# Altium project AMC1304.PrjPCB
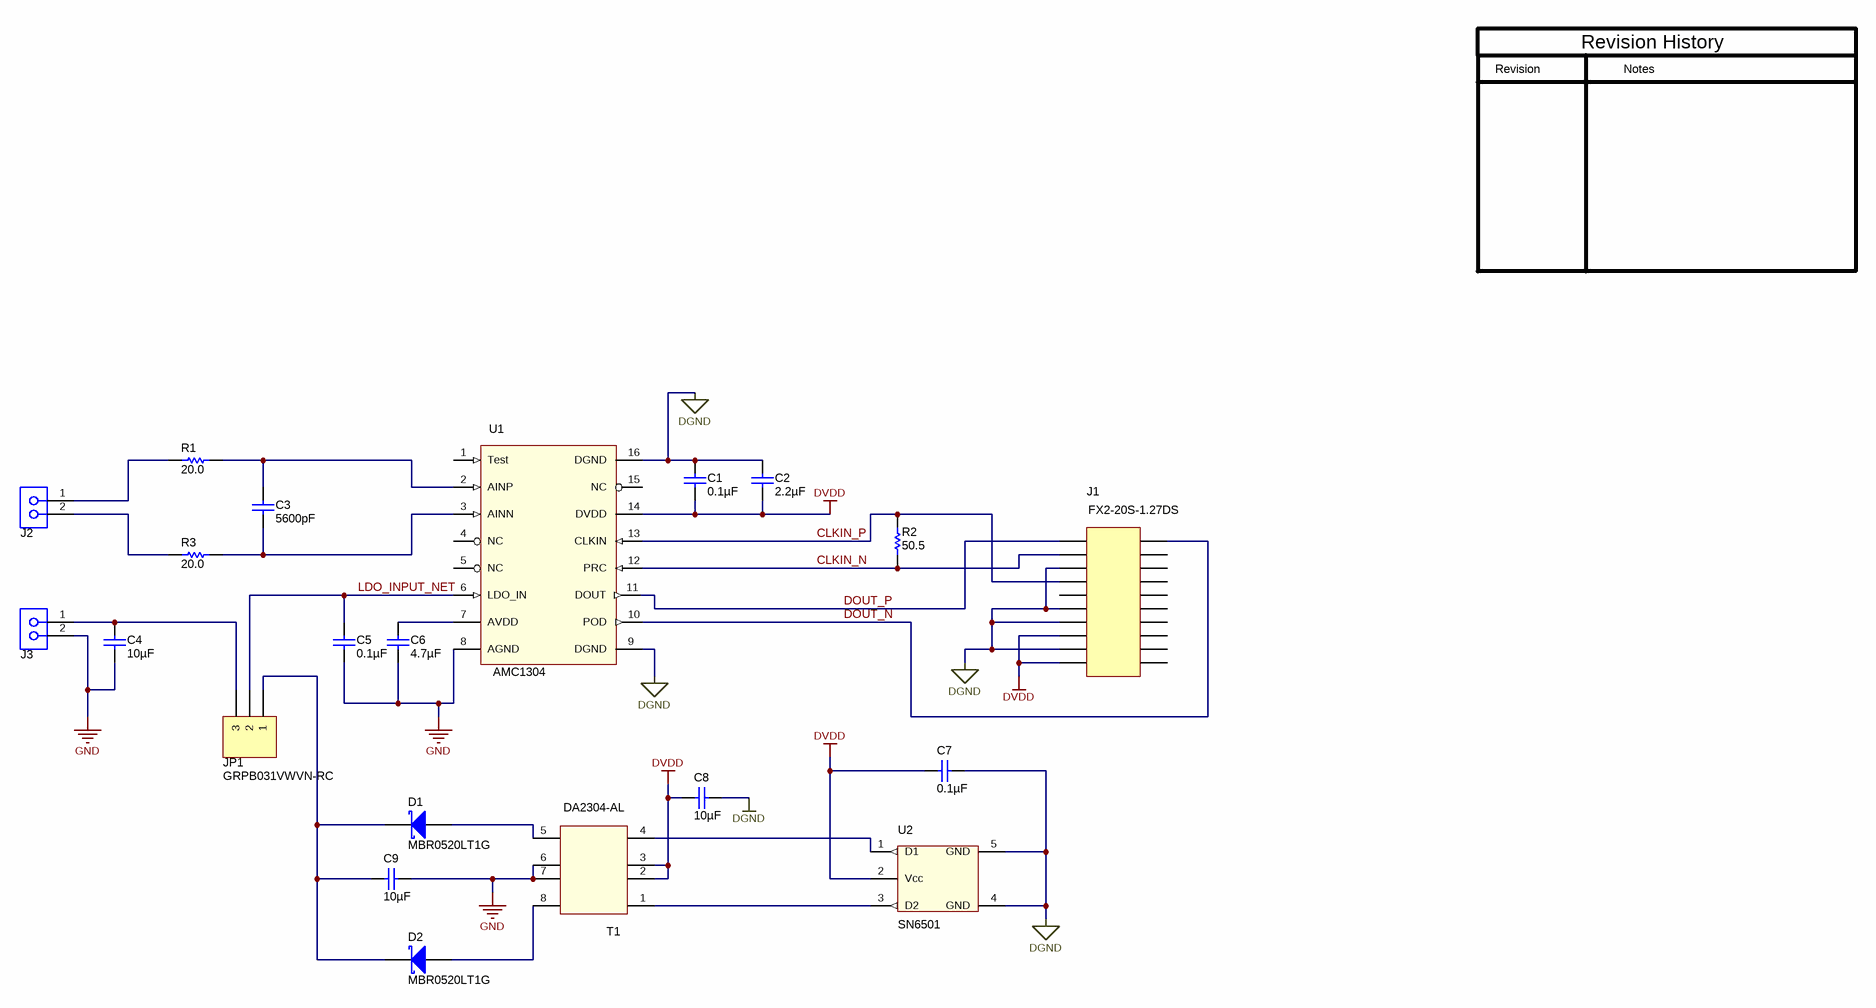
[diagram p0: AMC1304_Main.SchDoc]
CopyrightYear: 2014; PCB_Layout: Jose Duenas; PCB_Rev: E1; PRJ_Customer: Public Release; PRJ_Engineer: Jose Duenas; PRJ_Number: AMC1304EVM - TIPD; PRJ_Title: AMC1304 Evaluation Module - TIPD; SCH_Rev: E1; TechSupport: http://www.ti.com/support
1 sheet, 21 parts. Net scope: global (net labels, ports and power ports of the same name join across sheets).
Board file: AMC1304EVM.PcbDoc

## Sheet AMC1304_Main.SchDoc: Main Schematic
size 431 x 279 mm; Date: Not shown in title block; ApprovedBy: Not shown in title block; CheckedBy: Not shown in title block; Author: Not shown in title block; CompanyName: Not shown in title block; DrawnBy: Jose Duenas; Engineer: Not shown in title block; Organization: Not shown in title block; Address1: Not shown in title block; Address2: Not shown in title block; Address3: Not shown in title block; Address4: Not shown in title block; DocumentNumber: 2; Revision: Use project parameter SCH_Rev; SheetNumber: 2; SheetTotal: 3; PageSetup: Record=PageOptions|CenterHorizontal=True|CenterVertical=True|PrintScale=0.64|XCorrection=1.00|YCorrection=1.00|PrintKind=0|BorderSize=5000000|LeftOffset=0|BottomOffset=0|Orientation=2|PaperLength=1000|PaperWidth=1000|Scale=100|PaperSource=15|PrintQuality=600|MediaType=1|DitherType=10|PaperKind=Letter|PrintScaleMode=1

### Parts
C1  ValueDisplayed: 0.1µF  [1206]  (hidden comment: C3216C0G1E104J)
C2  ValueDisplayed: 2.2µF  [0805_HV]  (hidden comment: EMK212B7225KG-T)
C3  ValueDisplayed: 5600pF  [0805_HV]  (hidden comment: C2012C0G1E562J)
C4  ValueDisplayed: 10µF  [0805_HV]  (hidden comment: EMK212BJ106KG-T)
C5  ValueDisplayed: 0.1µF  [1206]  (hidden comment: C3216C0G1E104J)
C6  ValueDisplayed: 4.7µF  [0805_HV]  (hidden comment: C0805C475K8PACTU)
C7  ValueDisplayed: 0.1µF  [1206]  (hidden comment: C3216C0G1E104J)
C8  ValueDisplayed: 10µF  [0805_HV]  (hidden comment: EMK212BJ106KG-T)
C9  ValueDisplayed: 10µF  [0805_HV]  (hidden comment: EMK212BJ106KG-T)
D1  MBR0520LT1G  [SOD-123]
D2  MBR0520LT1G  [SOD-123]
J1  FX2-20S-1.27DS  [FX2_20S_1p27_DS_recept_good]
J2  1751248  [CONN_1751248]  (value not drawn)
J3  1751248  [CONN_1751248]  (value not drawn)
JP1  GRPB031VWVN-RC  [MHDR1X3]
R1  value 20.0  [0603]  (hidden comment: RT0603BRD0720RL)
R2  value 50.5  [0603]  (hidden comment: RT0603BRD0750R5L)
R3  value 20.0  [0603]  (hidden comment: RT0603BRD0720RL)
T1  DA2304-AL  [DA230x_land_patt]
U1  AMC1304  [DW0016_HV_ISO_JAD]
U2  SN6501  [DBV0005A_N]

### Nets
DGND: C1.1 C2.1 C7.2 C8.1 J1.a3 J1.a6 J1.a7 J1.a9 U1.9(DGND) U1.16(DGND) U2.4(GND) U2.5(GND)
DVDD: C1.2 C2.2 C7.1 C8.2 J1.a8 J1.a10 T1.2 T1.3 U1.14(DVDD) U2.2(Vcc)
GND: C4.2 C5.2 C6.2 C9.1 J3.2 T1.6 T1.7 U1.8(AGND)
CLKIN_N: J1.a2 R2.1 U1.12(PRC)
CLKIN_P: J1.a4 R2.2 U1.13(CLKIN)
DOUT_N: J1.b1 U1.10(POD)
DOUT_P: J1.a1 U1.11(DOUT)
LDO_INPUT_NET: C5.1 JP1.2 U1.6(LDO_IN)
NetC3_1: C3.1 R1.2 U1.2(AINP)
NetC3_2: C3.2 R3.2 U1.3(AINN)
NetC4_1: C4.1 J3.1 JP1.3
NetC6_1: C6.1 U1.7(AVDD)
NetC9_2: C9.2 D1.1(K) D2.1(K) JP1.1
NetD1_2: D1.2(A) T1.5
NetD2_2: D2.2(A) T1.8
NetJ2_1: J2.1 R1.1
NetJ2_2: J2.2 R3.1
NetT1_1: T1.1 U2.3(D2)
NetT1_4: T1.4 U2.1(D1)

Not connected (* = marked no-connect by the designer): J1 a5 b2 b3 b4 b5 b6 b7 b8 b9 b10; U1 1(Test) 4(NC) 5(NC) 15(NC)

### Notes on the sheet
- Revision
- Notes
- Revision History

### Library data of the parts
C1 C5 C7 = C3216C0G1E104J: CAP, CERM, 0.1uF, 25V, +/-5%, C0G/NP0, 1206; Manufacturer: TDK; Polarized: N; CompType: Capacitor; U/M: EA; Cap_F: 0.0000001; Tolerance_%: 5; VDC_V: 25; TaMin_C: -55; TaMax_C: 125
C2 = EMK212B7225KG-T: CAP, CERM, 2.2uF, 16V, +/-10%, X7R, 0805; Manufacturer: Taiyo Yuden; Polarized: N; CompType: Capacitor; U/M: EA; Cap_F: 0.0000022; Tolerance_%: 10; VDC_V: 16; TaMin_C: -55; TaMax_C: 125; Cap_Case: 0805
C3 = C2012C0G1E562J: CAP, CERM, 5600pF, 25V, +/-5%, C0G/NP0, 0805; Manufacturer: TDK; Polarized: N; CompType: Capacitor; U/M: EA; Cap_F: 0.0000000056; Tolerance_%: 5; VDC_V: 25; TaMin_C: -55; TaMax_C: 125; Cap_Case: 0805
C4 C8 C9 = EMK212BJ106KG-T: CAP, CERM, 10uF, 16V, +/-10%, X5R, 0805; Manufacturer: Taiyo Yuden; Polarized: N; CompType: Capacitor; U/M: EA; Cap_F: 0.00001; Tolerance_%: 10; VDC_V: 16; TaMin_C: -55; TaMax_C: 85; Cap_Case: 0805
C6 = C0805C475K8PACTU: CAP, CERM, 4.7uF, 10V, +/-10%, X5R, 0805; Manufacturer: Kemet; Polarized: N; CompType: Capacitor; U/M: EA; Cap_F: 0.0000047; Tolerance_%: 10; ESR_Ohm: 0.004; Value1: 0.004 ohm; IRMS_A: 9.89; TaMin_C: -55; TaMax_C: 85; Cap_Case: 0805
D1 D2 = MBR0520LT1G: Diode, Schottky, 20V, 0.5A, SOD-123; Manufacturer: ON Semiconductor; Alternate Manufacturer: Any; Alternate PartNumber: Equivalent; Value: 0.385V; U/M: EA; Vf_V: 0.385; Io_A: 0.5; Vr_V: 20; TJmax_C: 125; RJC_CperW: 150
J1 = FX2_20S_1p27_DS_recep_compon: 1.27mm Pitch Multi-function Two Piece Connector; Manufacturer: Hirose; SymbolCreator: Use a-id; CompType: Used in some BOM reports.  Useful for finding later.; U/M: EA, IN, or GM
J2 J3 = 1751248: Conn Term Block, 2POS, 3.5mm, TH; Manufacturer: Phoenix Contact; Alternate Manufacturer: Any; Alternate PartNumber: Equivalent; Value: 2x1; CompType: Terminal Block; U/M: EA
JP1 = MHDR1X3: Header, 3-Pin; Manufacturer: Sullins Connector Solutions
R1 R3 = RT0603BRD0720RL: RES, 20.0 ohm, 0.1%, 0.1W, 0603; Manufacturer: Yageo America; Alternate Manufacturer: Any; Alternate PartNumber: Equivalent; CompType: Resistor; Res_ohm: 20; Value_Code: 20R0; Tolerance_%: 0.1; VDC_V: 75; TempCo: 25 ppm/C; EIA_Code: E192; U/M: EA
R2 = RT0603BRD0750R5L: RES, 50.5 ohm, 0.1%, 0.1W, 0603; Manufacturer: Yageo America; Alternate Manufacturer: Any; Alternate PartNumber: Equivalent; CompType: Resistor; Value_Code: 50R5; Tolerance_%: 0.1; VDC_V: 75; TempCo: 25 ppm/C; EIA_Code: E192; U/M: EA
T1 = DA2304-AL_JAD: 1:2.2 Isolation Transformer; Manufacturer: Coilcraft; SymbolVersion: use current date i.e. 2008-05-20; SymbolCreator: Use a-id; CompType: Used in some BOM reports.  Useful for finding later.; U/M: EA, IN, or GM
U1 = AMC1304_JAD: AMC1304Mx in 16-pin DW (SOIC) package; Manufacturer: Texas Instruments; SymbolVersion: use current date i.e. 2008-05-20; SymbolCreator: Use a-id; CompType: Used in some BOM reports.  Useful for finding later.; U/M: EA, IN, or GM
U2 = SN6501_JAD: SN6501 transformer driver; Manufacturer: Texas Instruments; SymbolVersion: use current date i.e. 2008-05-20; SymbolCreator: Use a-id; CompType: Used in some BOM reports.  Useful for finding later.; U/M: EA, IN, or GM

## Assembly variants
CMOS_output: not fitted R3
LVDS_output: all parts fitted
